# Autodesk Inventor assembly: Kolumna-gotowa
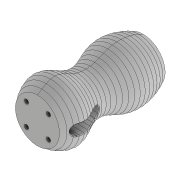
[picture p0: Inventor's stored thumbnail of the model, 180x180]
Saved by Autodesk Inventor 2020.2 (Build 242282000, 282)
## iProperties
Manager: www.cadconsulting.pl
Company: Fabian Stasiak CAD Consulting
Created: 2005-11
Part Number: Kolumna-gotowa
Document SubType Name: Assembly
Designer: F.Stasiak
Author: F.Stasiak
Subject: Zbiór ćwiczeń. Autodesk Inventor 2020. Kurs podstawowy
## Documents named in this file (6)
- C:\2020_Kurs_podstawowy\R6 Zespoły\Elementy\Kolumna-gotowa.iam
- C:\2020_Kurs_podstawowy\R6 Zespoły\Elementy\P1.ipt
- C:\2020_Kurs_podstawowy\R6 Zespoły\Elementy\P2.ipt
- C:\2020_Kurs_podstawowy\R6 Zespoły\Elementy\P3.ipt
- C:\2020_Kurs_podstawowy\R6 Zespoły\Elementy\P5.ipt
- C:\2020_Kurs_podstawowy\R6 Zespoły\Elementy\P6.ipt
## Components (24 placed, 5 different names)
1. P1:1 — Równoległy:1
2. P2:1 — Równoległy:1, Równoległy:2, Zestawiający:20, Równoległy:20
3. P3:1 — Równoległy:2, Zestawiający:21, Równoległy:21, Zestawiający:25
4. P3:2 — Zestawiający:2, Równoległy:4, Równoległy:5, Zestawiający:26, Równoległy:47, Równoległy:48
5. P3:3 — Zestawiający:2, Równoległy:4, Równoległy:5, Zestawiający:3, Równoległy:23, Równoległy:24
6. P2:2 — Zestawiający:3, Zestawiający:4, Równoległy:25, Równoległy:26
7. P1:2 — Zestawiający:4, Równoległy:6, Równoległy:27, Równoległy:28
8. P5:1 — Równoległy:6, Równoległy:7, Równoległy:29, Zestawiający:23
9. P6:1 — Równoległy:7, Zestawiający:5, Równoległy:8, Równoległy:9, Zestawiający:24, Równoległy:30
10. P6:2 — Zestawiający:5, Równoległy:8, Równoległy:9, Zestawiający:6, Równoległy:10, Równoległy:11
11. P6:3 — Zestawiający:6, Równoległy:10, Równoległy:11, Zestawiający:7
12. P5:2 — Zestawiający:7, Zestawiający:8, Równoległy:31, Równoległy:32, Równoległy:33, Równoległy:34
13. P5:3 — Zestawiający:8, Zestawiający:9, Równoległy:33, Równoległy:34
14. P1:3 — Zestawiający:9, Zestawiający:10, Równoległy:35, Równoległy:36
15. P2:3 — Zestawiający:10, Zestawiający:11, Równoległy:37, Równoległy:38
16. P3:4 — Zestawiający:11, Zestawiający:12, Równoległy:12, Równoległy:13, Równoległy:39, Równoległy:40
17. P3:5 — Zestawiający:12, Równoległy:12, Równoległy:13, Zestawiający:13, Równoległy:14, Równoległy:15
18. P3:6 — Zestawiający:13, Równoległy:14, Równoległy:15, Zestawiający:14, Równoległy:16, Równoległy:17, Równoległy:18
19. P3:7 — Zestawiający:14, Równoległy:16, Równoległy:17, Zestawiający:15, Równoległy:19
20. P3:8 — Zestawiający:15, Równoległy:18, Równoległy:19, Zestawiający:16
21. P2:4 — Zestawiający:16, Zestawiający:17, Równoległy:41, Równoległy:42
22. P1:4 — Zestawiający:17, Zestawiający:18, Równoległy:43, Równoległy:44
23. P5:4 — Zestawiający:18, Równoległy:45, Równoległy:46
24. P3:9 — Zestawiający:25, Zestawiający:26, Równoległy:47, Równoległy:48
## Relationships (69: Flush 46, Mate 23)
- Równoległy:1 [Flush]: P1:1 ↔ P2:1
- Równoległy:2 [Flush]: P2:1 ↔ P3:1
- Zestawiający:2 [Mate]: P3:2 ↔ P3:3
- Równoległy:4 [Flush]: P3:2 ↔ P3:3
- Równoległy:5 [Flush]: P3:2 ↔ P3:3
- Zestawiający:3 [Mate]: P3:3 ↔ P2:2
- Zestawiający:4 [Mate]: P2:2 ↔ P1:2
- Równoległy:6 [Flush]: P1:2 ↔ P5:1
- Równoległy:7 [Flush]: P5:1 ↔ P6:1
- Zestawiający:5 [Mate]: P6:1 ↔ P6:2
- Równoległy:8 [Flush]: P6:1 ↔ P6:2
- Równoległy:9 [Flush]: P6:1 ↔ P6:2
- Zestawiający:6 [Mate]: P6:2 ↔ P6:3
- Równoległy:10 [Flush]: P6:2 ↔ P6:3
- Równoległy:11 [Flush]: P6:2 ↔ P6:3
- Zestawiający:7 [Mate]: P6:3 ↔ P5:2
- Zestawiający:8 [Mate]: P5:2 ↔ P5:3
- Zestawiający:9 [Mate]: P5:3 ↔ P1:3
- Zestawiający:10 [Mate]: P1:3 ↔ P2:3
- Zestawiający:11 [Mate]: P2:3 ↔ P3:4
- Zestawiający:12 [Mate]: P3:4 ↔ P3:5
- Równoległy:12 [Flush]: P3:4 ↔ P3:5
- Równoległy:13 [Flush]: P3:4 ↔ P3:5
- Zestawiający:13 [Mate]: P3:5 ↔ P3:6
- Równoległy:14 [Flush]: P3:5 ↔ P3:6
- Równoległy:15 [Flush]: P3:5 ↔ P3:6
- Zestawiający:14 [Mate]: P3:6 ↔ P3:7
- Równoległy:16 [Flush]: P3:6 ↔ P3:7
- Równoległy:17 [Flush]: P3:6 ↔ P3:7
- Zestawiający:15 [Mate]: P3:7 ↔ P3:8
- Równoległy:18 [Flush]: P3:6 ↔ P3:8
- Równoległy:19 [Flush]: P3:7 ↔ P3:8
- Zestawiający:16 [Mate]: P3:8 ↔ P2:4
- Zestawiający:17 [Mate]: P2:4 ↔ P1:4
- Zestawiający:18 [Mate]: P1:4 ↔ P5:4
- Zestawiający:20 [Mate]: P2:1
- Równoległy:20 [Flush]: P2:1
- Zestawiający:21 [Mate]: P3:1
- Równoległy:21 [Flush]: P3:1
- Równoległy:23 [Flush]: P3:3
- Równoległy:24 [Flush]: P3:3
- Równoległy:25 [Flush]: P2:2
- Równoległy:26 [Flush]: P2:2
- Równoległy:27 [Flush]: P1:2
- Równoległy:28 [Flush]: P1:2
- Równoległy:29 [Flush]: P5:1
- Zestawiający:23 [Mate]: P5:1
- Zestawiający:24 [Mate]: P6:1
- Równoległy:30 [Flush]: P6:1
- Równoległy:31 [Flush]: P5:2
- Równoległy:32 [Flush]: P5:2
- Równoległy:33 [Flush]: P5:2 ↔ P5:3
- Równoległy:34 [Flush]: P5:2 ↔ P5:3
- Równoległy:35 [Flush]: P1:3
- Równoległy:36 [Flush]: P1:3
- Równoległy:37 [Flush]: P2:3
- Równoległy:38 [Flush]: P2:3
- Równoległy:39 [Flush]: P3:4
- Równoległy:40 [Flush]: P3:4
- Równoległy:41 [Flush]: P2:4
- Równoległy:42 [Flush]: P2:4
- Równoległy:43 [Flush]: P1:4
- Równoległy:44 [Flush]: P1:4
- Równoległy:45 [Flush]: P5:4
- Równoległy:46 [Flush]: P5:4
- Zestawiający:25 [Mate]: P3:1 ↔ P3:9
- Zestawiający:26 [Mate]: P3:2 ↔ P3:9
- Równoległy:47 [Flush]: P3:2 ↔ P3:9
- Równoległy:48 [Flush]: P3:2 ↔ P3:9
